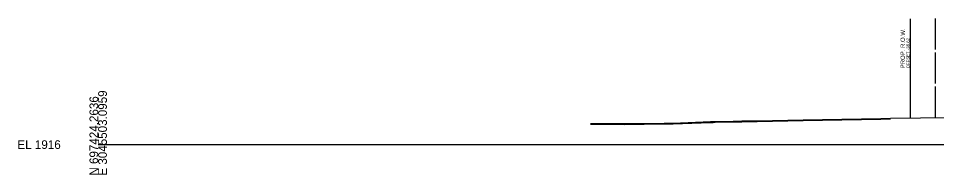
# Model space of a CAD drawing. Extents: x 1574 to 14903, y 7971 to 16537.
# Drawn here: x 14274.3 to 14569.8, y 7990.3 to 8040.7 of the extents above; entities that cross this region are included whole.
import ezdxf

# ---------------------------------------------------------------- set-up
doc = ezdxf.new("R2010")
doc.units = 0
for name, color, linetype in [('DESIGN - ROW - Right-of-Way and Easement Labels', 7, 'Continuous'), ('DESIGN - ROW - Right-of-Way Linework', 7, 'Continuous'), ('DESIGN - SHEET - Light Grid', 7, 'Continuous'), ('SURVEY - GROUND - Bottom of Topsoil Layer', 7, 'Continuous'), ('SURVEY - GROUND - Top of Ground', 7, 'Continuous'), ('SURVEY - PROPERTY - ROW Lines', 7, 'Continuous')]:
    doc.layers.add(name, color=color, linetype=linetype)

msp = doc.modelspace()

# ---------------------------------------------------------------- linework, layer by layer
at = {"layer": 'DESIGN - ROW - Right-of-Way Linework'}
msp.add_line((14561.38, 8008.61), (14561.38, 8040.61), dxfattribs=at)
at = {"layer": 'DESIGN - SHEET - Light Grid'}
msp.add_line((14300, 8000), (14600, 8000), dxfattribs=at)
at = {"layer": 'SURVEY - GROUND - Bottom of Topsoil Layer'}
for p, q in [((14458.44, 8006.57), (14469.38, 8006.51)), ((14469.38, 8006.51), (14482.13, 8006.65)), ((14482.13, 8006.65), (14483.57, 8006.66)), ((14483.57, 8006.66), (14485.05, 8006.68)), ((14485.05, 8006.68), (14497.07, 8007.15)), ((14497.07, 8007.15), (14497.92, 8007.18)), ((14497.92, 8007.18), (14498.61, 8007.2)), ((14498.61, 8007.2), (14504.33, 8007.35)), ((14504.33, 8007.35), (14507.13, 8007.37)), ((14507.13, 8007.37), (14516.96, 8007.52)), ((14516.96, 8007.52), (14526.84, 8007.77)), ((14526.84, 8007.77), (14533.07, 8007.86)), ((14533.07, 8007.86), (14551.85, 8008.2)), ((14551.85, 8008.2), (14555, 8008.27))]:
    msp.add_line(p, q, dxfattribs=at)
at = {"layer": 'SURVEY - GROUND - Top of Ground'}
msp.add_lwpolyline([(14458.44, 8006.82), (14469.38, 8006.76), (14482.13, 8006.9), (14483.57, 8006.91), (14485.05, 8006.93), (14497.07, 8007.4), (14497.92, 8007.43), (14498.61, 8007.45), (14504.33, 8007.6), (14507.13, 8007.62), (14516.96, 8007.77), (14526.84, 8008.02), (14533.07, 8008.11), (14551.85, 8008.45), (14555, 8008.52), (14574.32, 8008.79)], dxfattribs=at)
at = {"layer": 'SURVEY - PROPERTY - ROW Lines'}
for p, q in [((14569.47, 8030.72), (14569.47, 8040.72)), ((14569.47, 8019.72), (14569.47, 8029.72)), ((14569.47, 8008.72), (14569.47, 8018.72))]:
    msp.add_line(p, q, dxfattribs=at)

# ---------------------------------------------------------------- texts
at = {"layer": 'DESIGN - ROW - Right-of-Way and Easement Labels'}
for s, height, p in [('PROP. R.O.W.', 1.4, (14559.63, 8024.61)), ('OFFSET -38.62', 1, (14561.13, 8024.61))]:
    msp.add_text(s, height=height, rotation=90, dxfattribs=at).set_placement(p)
at = {"layer": 'DESIGN - SHEET - Light Grid'}
for s, p in [('N 697424.2636', (14300, 7990)), ('E 3045503.0959', (14302.8, 7990))]:
    msp.add_text(s, height=2.8, rotation=90, dxfattribs=at).set_placement(p)
msp.add_text('EL 1916', height=2.8, dxfattribs=at).set_placement((14274, 7998.6))

doc.saveas('drawing.dxf')
